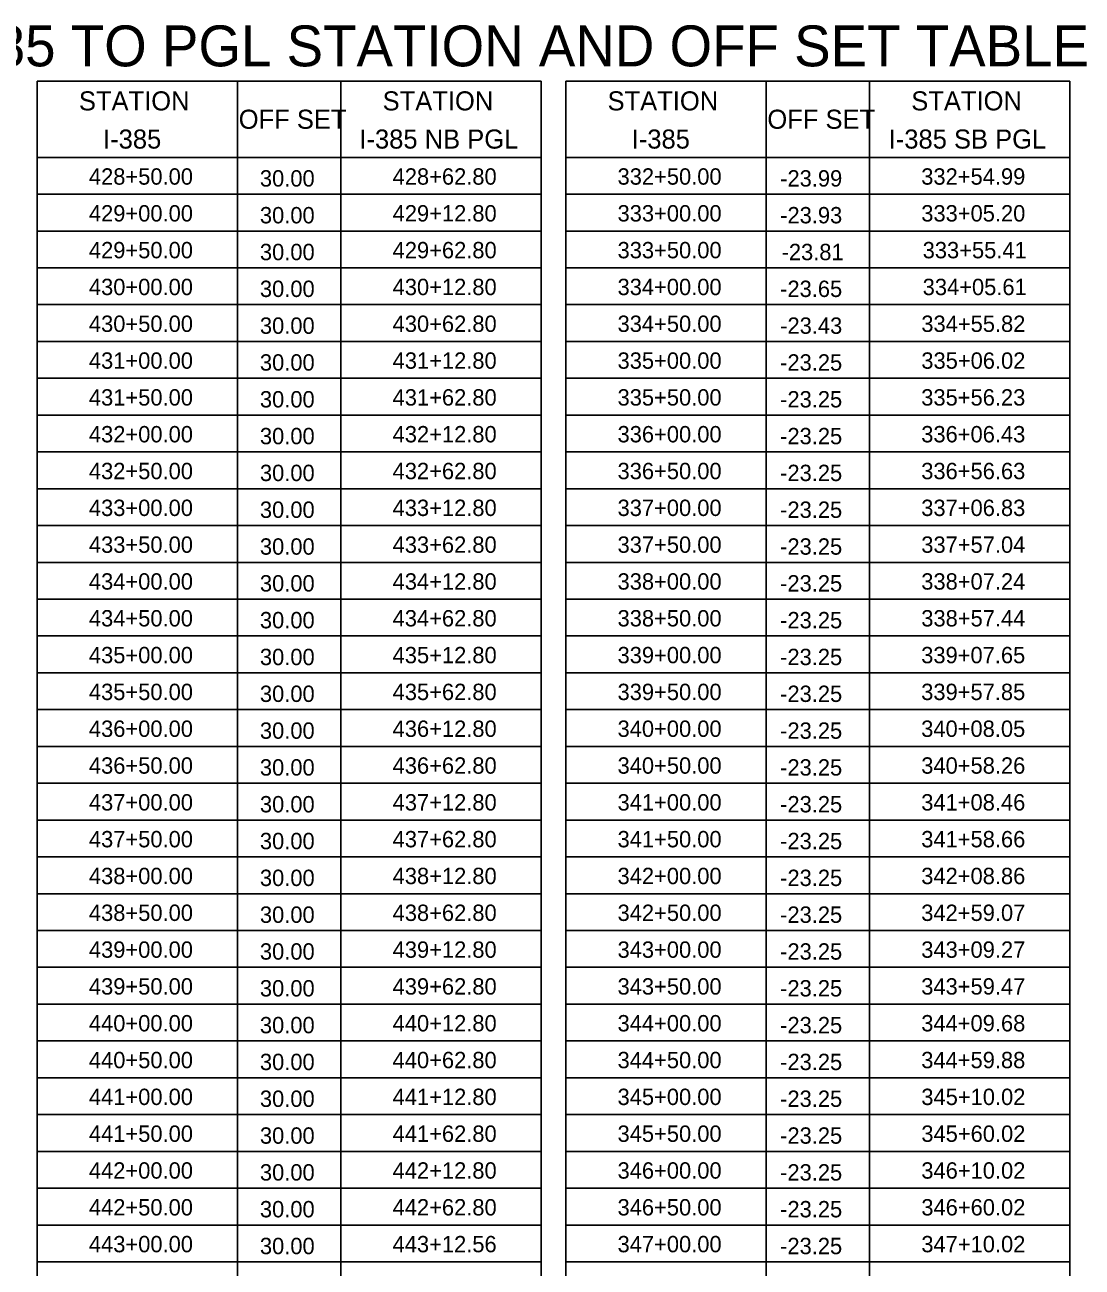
# Model space of a CAD drawing. Extents: x 1602163 to 1612907, y 1087635 to 1096265.
# Drawn here: x 1610181.3 to 1610569, y 1095754.9 to 1096210.5 of the extents above; entities that cross this region are included whole.
import ezdxf

# ---------------------------------------------------------------- set-up
doc = ezdxf.new("R2010")
doc.units = 0
doc.layers.add('RD_SHT_Misc1', color=7, linetype='Continuous')
doc.layers.add('RD_SHT_TX', color=7, linetype='Continuous')

msp = doc.modelspace()

# ---------------------------------------------------------------- linework, layer by layer
at = {"layer": 'RD_SHT_Misc1'}
for p, q in [((1610185.83, 1096189.84), (1610185.83, 1095297.84)), ((1610185.83, 1096189.84), (1610370.66, 1096189.84)), ((1610259.3, 1096189.84), (1610259.3, 1095297.84)), ((1610297.19, 1096189.84), (1610297.19, 1095297.84)), ((1610370.66, 1096189.84), (1610370.66, 1095297.84)), ((1610379.66, 1096189.84), (1610379.66, 1095297.84)), ((1610379.66, 1096189.84), (1610564.49, 1096189.84)), ((1610453.13, 1096189.84), (1610453.13, 1095297.84)), ((1610491.02, 1096189.84), (1610491.02, 1095297.84)), ((1610564.49, 1096189.84), (1610564.49, 1095297.84)), ((1610185.83, 1096161.84), (1610370.66, 1096161.84)), ((1610379.66, 1096161.84), (1610564.49, 1096161.84)), ((1610185.83, 1096148.34), (1610370.66, 1096148.34)), ((1610379.66, 1096148.34), (1610564.49, 1096148.34)), ((1610185.83, 1096134.84), (1610370.66, 1096134.84)), ((1610379.66, 1096134.84), (1610564.49, 1096134.84)), ((1610185.83, 1096121.34), (1610370.66, 1096121.34)), ((1610379.66, 1096121.34), (1610564.49, 1096121.34)), ((1610185.83, 1096107.84), (1610370.66, 1096107.84)), ((1610379.66, 1096107.84), (1610564.49, 1096107.84)), ((1610185.83, 1096094.34), (1610370.66, 1096094.34)), ((1610379.66, 1096094.34), (1610564.49, 1096094.34)), ((1610185.83, 1096080.84), (1610370.66, 1096080.84)), ((1610379.66, 1096080.84), (1610564.49, 1096080.84)), ((1610185.83, 1096067.34), (1610370.66, 1096067.34)), ((1610379.66, 1096067.34), (1610564.49, 1096067.34)), ((1610185.83, 1096053.84), (1610370.66, 1096053.84)), ((1610379.66, 1096053.84), (1610564.49, 1096053.84)), ((1610185.83, 1096040.34), (1610370.66, 1096040.34)), ((1610379.66, 1096040.34), (1610564.49, 1096040.34)), ((1610185.83, 1096026.84), (1610370.66, 1096026.84)), ((1610379.66, 1096026.84), (1610564.49, 1096026.84)), ((1610185.83, 1096013.34), (1610370.66, 1096013.34)), ((1610379.66, 1096013.34), (1610564.49, 1096013.34)), ((1610185.83, 1095999.84), (1610370.66, 1095999.84)), ((1610379.66, 1095999.84), (1610564.49, 1095999.84)), ((1610185.83, 1095986.34), (1610370.66, 1095986.34)), ((1610379.66, 1095986.34), (1610564.49, 1095986.34)), ((1610185.83, 1095972.84), (1610370.66, 1095972.84)), ((1610379.66, 1095972.84), (1610564.49, 1095972.84)), ((1610185.83, 1095959.34), (1610370.66, 1095959.34)), ((1610379.66, 1095959.34), (1610564.49, 1095959.34)), ((1610185.83, 1095945.84), (1610370.66, 1095945.84)), ((1610379.66, 1095945.84), (1610564.49, 1095945.84)), ((1610185.83, 1095932.34), (1610370.66, 1095932.34)), ((1610379.66, 1095932.34), (1610564.49, 1095932.34)), ((1610185.83, 1095918.84), (1610370.66, 1095918.84)), ((1610379.66, 1095918.84), (1610564.49, 1095918.84)), ((1610185.83, 1095905.34), (1610370.66, 1095905.34)), ((1610379.66, 1095905.34), (1610564.49, 1095905.34)), ((1610185.83, 1095891.84), (1610370.66, 1095891.84)), ((1610379.66, 1095891.84), (1610564.49, 1095891.84)), ((1610185.83, 1095878.34), (1610370.66, 1095878.34)), ((1610379.66, 1095878.34), (1610564.49, 1095878.34)), ((1610185.83, 1095864.84), (1610370.66, 1095864.84)), ((1610379.66, 1095864.84), (1610564.49, 1095864.84)), ((1610185.83, 1095851.34), (1610370.66, 1095851.34)), ((1610379.66, 1095851.34), (1610564.49, 1095851.34)), ((1610185.83, 1095837.84), (1610370.66, 1095837.84)), ((1610379.66, 1095837.84), (1610564.49, 1095837.84)), ((1610185.83, 1095824.34), (1610370.66, 1095824.34)), ((1610379.66, 1095824.34), (1610564.49, 1095824.34)), ((1610185.83, 1095810.84), (1610370.66, 1095810.84)), ((1610379.66, 1095810.84), (1610564.49, 1095810.84)), ((1610185.83, 1095797.34), (1610370.66, 1095797.34)), ((1610379.66, 1095797.34), (1610564.49, 1095797.34)), ((1610185.83, 1095783.84), (1610370.66, 1095783.84)), ((1610379.66, 1095783.84), (1610564.49, 1095783.84)), ((1610185.83, 1095770.34), (1610370.66, 1095770.34)), ((1610379.66, 1095770.34), (1610564.49, 1095770.34)), ((1610185.83, 1095756.84), (1610370.66, 1095756.84)), ((1610379.66, 1095756.84), (1610564.49, 1095756.84))]:
    msp.add_line(p, q, dxfattribs=at)

# ---------------------------------------------------------------- texts
at = {"layer": 'RD_SHT_TX'}
for s, height, p in [('I-385 TO PGL STATION AND OFF SET TABLES', 15, (1610146.87, 1096195.23)), ('STATION', 7, (1610201.15, 1096179.07)), ('STATION', 7, (1610312.51, 1096179.07)), ('STATION', 7, (1610394.98, 1096179.07)), ('STATION', 7, (1610506.34, 1096179.07)), ('OFF SET', 7, (1610259.75, 1096172.34)), ('OFF SET', 7, (1610453.58, 1096172.34)), ('I-385', 7, (1610210.01, 1096165.07)), ('I-385 NB PGL', 7, (1610303.99, 1096165.07)), ('I-385', 7, (1610403.84, 1096165.07)), ('I-385 SB PGL', 7, (1610498.06, 1096165.07)), ('428+50.00', 6, (1610204.82, 1096151.84)), ('428+62.80', 6, (1610316.18, 1096151.84)), ('332+50.00', 6, (1610398.65, 1096151.84)), ('332+54.99', 6, (1610510, 1096151.84)), ('30.00', 6, (1610267.52, 1096151.15)), ('-23.99', 6, (1610458.28, 1096151.15)), ('429+00.00', 6, (1610204.82, 1096138.34)), ('429+12.80', 6, (1610316.18, 1096138.34)), ('333+00.00', 6, (1610398.65, 1096138.34)), ('333+05.20', 6, (1610510.01, 1096138.34)), ('30.00', 6, (1610267.52, 1096137.65)), ('-23.93', 6, (1610458.28, 1096137.65)), ('429+50.00', 6, (1610204.82, 1096124.84)), ('429+62.80', 6, (1610316.18, 1096124.84)), ('333+50.00', 6, (1610398.65, 1096124.84)), ('333+55.41', 6, (1610510.52, 1096124.84)), ('30.00', 6, (1610267.52, 1096124.15)), ('-23.81', 6, (1610458.8, 1096124.15)), ('430+00.00', 6, (1610204.82, 1096111.34)), ('30.00', 6, (1610267.52, 1096110.65)), ('430+12.80', 6, (1610316.18, 1096111.34)), ('334+00.00', 6, (1610398.65, 1096111.34)), ('-23.65', 6, (1610458.26, 1096110.65)), ('334+05.61', 6, (1610510.52, 1096111.34)), ('430+50.00', 6, (1610204.82, 1096097.84)), ('30.00', 6, (1610267.52, 1096097.15)), ('430+62.80', 6, (1610316.18, 1096097.84)), ('334+50.00', 6, (1610398.65, 1096097.84)), ('-23.43', 6, (1610458.28, 1096097.15)), ('334+55.82', 6, (1610510.03, 1096097.84)), ('431+00.00', 6, (1610204.82, 1096084.34)), ('30.00', 6, (1610267.52, 1096083.65)), ('431+12.80', 6, (1610316.18, 1096084.34)), ('335+00.00', 6, (1610398.65, 1096084.34)), ('-23.25', 6, (1610458.26, 1096083.65)), ('335+06.02', 6, (1610510.03, 1096084.34)), ('431+50.00', 6, (1610204.82, 1096070.84)), ('30.00', 6, (1610267.52, 1096070.15)), ('431+62.80', 6, (1610316.18, 1096070.84)), ('335+50.00', 6, (1610398.65, 1096070.84)), ('-23.25', 6, (1610458.26, 1096070.15)), ('335+56.23', 6, (1610510, 1096070.84)), ('432+00.00', 6, (1610204.82, 1096057.34)), ('30.00', 6, (1610267.52, 1096056.65)), ('432+12.80', 6, (1610316.18, 1096057.34)), ('336+00.00', 6, (1610398.65, 1096057.34)), ('-23.25', 6, (1610458.26, 1096056.65)), ('336+06.43', 6, (1610510, 1096057.34)), ('432+50.00', 6, (1610204.82, 1096043.84)), ('30.00', 6, (1610267.52, 1096043.15)), ('432+62.80', 6, (1610316.18, 1096043.84)), ('336+50.00', 6, (1610398.65, 1096043.84)), ('-23.25', 6, (1610458.26, 1096043.15)), ('336+56.63', 6, (1610510, 1096043.84)), ('433+00.00', 6, (1610204.82, 1096030.34)), ('30.00', 6, (1610267.52, 1096029.65)), ('433+12.80', 6, (1610316.18, 1096030.34)), ('337+00.00', 6, (1610398.65, 1096030.34)), ('-23.25', 6, (1610458.26, 1096029.65)), ('337+06.83', 6, (1610510, 1096030.34)), ('433+50.00', 6, (1610204.82, 1096016.84)), ('30.00', 6, (1610267.52, 1096016.15)), ('433+62.80', 6, (1610316.18, 1096016.84)), ('337+50.00', 6, (1610398.65, 1096016.84)), ('-23.25', 6, (1610458.26, 1096016.15)), ('337+57.04', 6, (1610510.01, 1096016.84)), ('434+00.00', 6, (1610204.82, 1096003.34)), ('30.00', 6, (1610267.52, 1096002.65)), ('434+12.80', 6, (1610316.18, 1096003.34)), ('338+00.00', 6, (1610398.65, 1096003.34)), ('-23.25', 6, (1610458.26, 1096002.65)), ('338+07.24', 6, (1610510.01, 1096003.34)), ('434+50.00', 6, (1610204.82, 1095989.84)), ('30.00', 6, (1610267.52, 1095989.15)), ('434+62.80', 6, (1610316.18, 1095989.84)), ('338+50.00', 6, (1610398.65, 1095989.84)), ('-23.25', 6, (1610458.26, 1095989.15)), ('338+57.44', 6, (1610510.01, 1095989.84)), ('435+00.00', 6, (1610204.82, 1095976.34)), ('30.00', 6, (1610267.52, 1095975.65)), ('435+12.80', 6, (1610316.18, 1095976.34)), ('339+00.00', 6, (1610398.65, 1095976.34)), ('-23.25', 6, (1610458.26, 1095975.65)), ('339+07.65', 6, (1610509.98, 1095976.34)), ('435+50.00', 6, (1610204.82, 1095962.84)), ('30.00', 6, (1610267.52, 1095962.15)), ('435+62.80', 6, (1610316.18, 1095962.84)), ('339+50.00', 6, (1610398.65, 1095962.84)), ('-23.25', 6, (1610458.26, 1095962.15)), ('339+57.85', 6, (1610509.98, 1095962.84)), ('436+00.00', 6, (1610204.82, 1095949.34)), ('30.00', 6, (1610267.52, 1095948.65)), ('436+12.80', 6, (1610316.18, 1095949.34)), ('340+00.00', 6, (1610398.65, 1095949.34)), ('-23.25', 6, (1610458.26, 1095948.65)), ('340+08.05', 6, (1610509.98, 1095949.34)), ('436+50.00', 6, (1610204.82, 1095935.84)), ('30.00', 6, (1610267.52, 1095935.15)), ('436+62.80', 6, (1610316.18, 1095935.84)), ('340+50.00', 6, (1610398.65, 1095935.84)), ('-23.25', 6, (1610458.26, 1095935.15)), ('340+58.26', 6, (1610510, 1095935.84)), ('437+00.00', 6, (1610204.82, 1095922.34)), ('30.00', 6, (1610267.52, 1095921.65)), ('437+12.80', 6, (1610316.18, 1095922.34)), ('341+00.00', 6, (1610398.65, 1095922.34)), ('-23.25', 6, (1610458.26, 1095921.65)), ('341+08.46', 6, (1610510, 1095922.34)), ('437+50.00', 6, (1610204.82, 1095908.84)), ('30.00', 6, (1610267.52, 1095908.15)), ('437+62.80', 6, (1610316.18, 1095908.84)), ('341+50.00', 6, (1610398.65, 1095908.84)), ('-23.25', 6, (1610458.26, 1095908.15)), ('341+58.66', 6, (1610510, 1095908.84)), ('438+00.00', 6, (1610204.82, 1095895.34)), ('30.00', 6, (1610267.52, 1095894.65)), ('438+12.80', 6, (1610316.18, 1095895.34)), ('342+00.00', 6, (1610398.65, 1095895.34)), ('-23.25', 6, (1610458.26, 1095894.65)), ('342+08.86', 6, (1610510, 1095895.34)), ('438+50.00', 6, (1610204.82, 1095881.84)), ('30.00', 6, (1610267.52, 1095881.15)), ('438+62.80', 6, (1610316.18, 1095881.84)), ('342+50.00', 6, (1610398.65, 1095881.84)), ('-23.25', 6, (1610458.26, 1095881.15)), ('342+59.07', 6, (1610510, 1095881.84)), ('439+00.00', 6, (1610204.82, 1095868.34)), ('30.00', 6, (1610267.52, 1095867.65)), ('439+12.80', 6, (1610316.18, 1095868.34)), ('343+00.00', 6, (1610398.65, 1095868.34)), ('-23.25', 6, (1610458.26, 1095867.65)), ('343+09.27', 6, (1610510, 1095868.34)), ('439+50.00', 6, (1610204.82, 1095854.84)), ('30.00', 6, (1610267.52, 1095854.15)), ('439+62.80', 6, (1610316.18, 1095854.84)), ('343+50.00', 6, (1610398.65, 1095854.84)), ('-23.25', 6, (1610458.26, 1095854.15)), ('343+59.47', 6, (1610510, 1095854.84)), ('440+00.00', 6, (1610204.82, 1095841.34)), ('30.00', 6, (1610267.52, 1095840.65)), ('440+12.80', 6, (1610316.18, 1095841.34)), ('344+00.00', 6, (1610398.65, 1095841.34)), ('-23.25', 6, (1610458.26, 1095840.65)), ('344+09.68', 6, (1610510, 1095841.34)), ('440+50.00', 6, (1610204.82, 1095827.84)), ('30.00', 6, (1610267.52, 1095827.15)), ('440+62.80', 6, (1610316.18, 1095827.84)), ('344+50.00', 6, (1610398.65, 1095827.84)), ('-23.25', 6, (1610458.26, 1095827.15)), ('344+59.88', 6, (1610510, 1095827.84)), ('441+00.00', 6, (1610204.82, 1095814.34)), ('30.00', 6, (1610267.52, 1095813.65)), ('441+12.80', 6, (1610316.18, 1095814.34)), ('345+00.00', 6, (1610398.65, 1095814.34)), ('-23.25', 6, (1610458.26, 1095813.65)), ('345+10.02', 6, (1610510.03, 1095814.34)), ('441+50.00', 6, (1610204.82, 1095800.84)), ('30.00', 6, (1610267.52, 1095800.15)), ('441+62.80', 6, (1610316.18, 1095800.84)), ('345+50.00', 6, (1610398.65, 1095800.84)), ('-23.25', 6, (1610458.26, 1095800.15)), ('345+60.02', 6, (1610510.03, 1095800.84)), ('442+00.00', 6, (1610204.82, 1095787.34)), ('442+12.80', 6, (1610316.18, 1095787.34)), ('346+00.00', 6, (1610398.65, 1095787.34)), ('346+10.02', 6, (1610510.03, 1095787.34)), ('30.00', 6, (1610267.52, 1095786.65)), ('-23.25', 6, (1610458.26, 1095786.65)), ('442+50.00', 6, (1610204.82, 1095773.84)), ('442+62.80', 6, (1610316.18, 1095773.84)), ('346+50.00', 6, (1610398.65, 1095773.84)), ('346+60.02', 6, (1610510.03, 1095773.84)), ('30.00', 6, (1610267.52, 1095773.15)), ('-23.25', 6, (1610458.26, 1095773.15)), ('443+00.00', 6, (1610204.82, 1095760.34)), ('443+12.56', 6, (1610316.17, 1095760.34)), ('347+00.00', 6, (1610398.65, 1095760.34)), ('347+10.02', 6, (1610510.03, 1095760.34)), ('30.00', 6, (1610267.52, 1095759.65)), ('-23.25', 6, (1610458.26, 1095759.65))]:
    msp.add_text(s, height=height, dxfattribs=at).set_placement(p)

doc.saveas('drawing.dxf')
